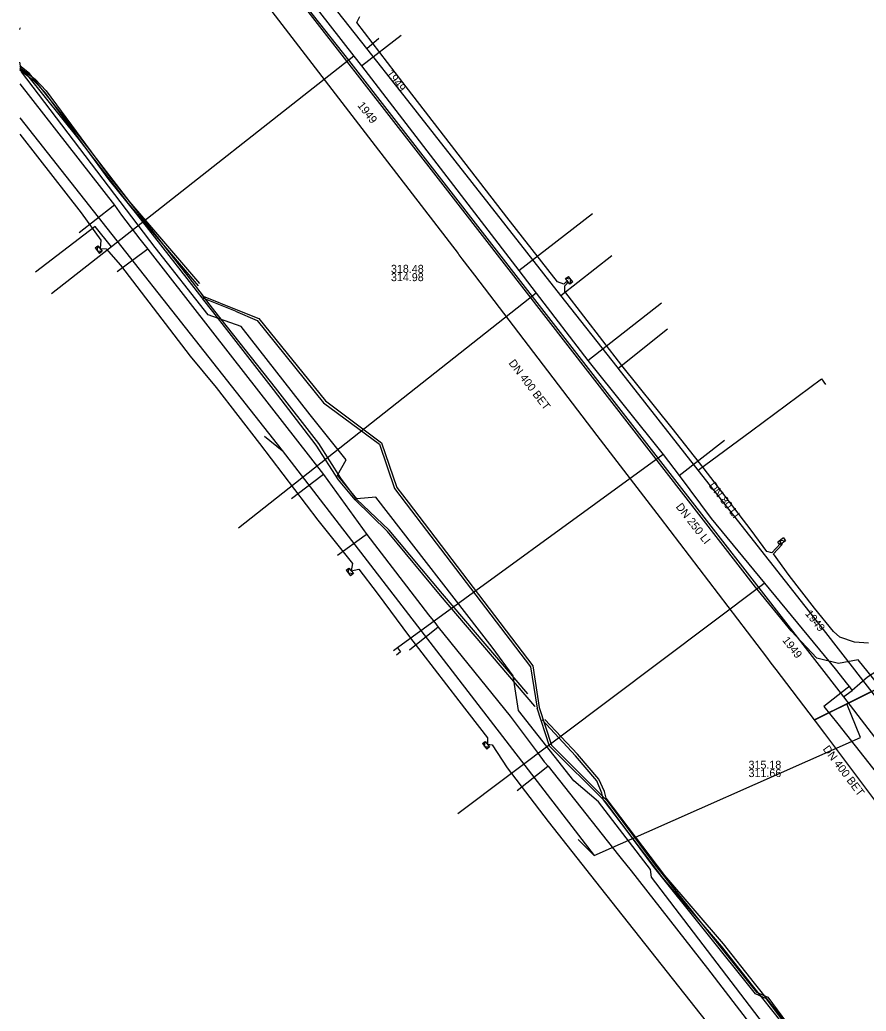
# Model space of a CAD drawing. Extents: x -600391 to -599491, y -1160176 to -1159402.
# Drawn here: x -600391 to -600306.4, y -1160007 to -1159907.9 of the extents above; entities that cross this region are included whole.
import ezdxf

# ---------------------------------------------------------------- set-up
doc = ezdxf.new("R2010")
doc.units = 0
for name, color, linetype in [('31', 7, 'Continuous'), ('Vrstva 1', 7, 'Continuous'), ('Vrstva 12', 7, 'Continuous'), ('Vrstva 13', 7, 'Continuous'), ('Vrstva 15', 7, 'Continuous'), ('Vrstva 16', 7, 'Continuous'), ('Vrstva 19', 7, 'Continuous'), ('Vrstva 42', 7, 'Continuous'), ('Vrstva 43', 7, 'Continuous'), ('Vrstva 44', 7, 'Continuous'), ('Vrstva 55', 7, 'Continuous'), ('Vrstva 9', 7, 'Continuous')]:
    doc.layers.add(name, color=color, linetype=linetype)

# ---------------------------------------------------------------- blocks, each defined once
blk = doc.blocks.new('NN630')
at = {"layer": '31'}
for points in [[(0, -0.7), (-0.7, 0)], [(-0.7, -0.7), (-0.7, 0), (0.7, 0), (0.7, -0.7)], [(-0.7, -0.7), (0.7, -0.7)], [(0, -0.7), (0.7, 0)]]:
    blk.add_lwpolyline(points, dxfattribs=at)

msp = doc.modelspace()

# ---------------------------------------------------------------- linework, layer by layer
at = {"layer": 'Vrstva 1'}
for points in [[(-600391.008, -1159917.713), (-600364.77, -1159950.97), (-600333.59, -1159991.48), (-600306.97, -1159979.68), (-600308.31, -1159976.3)], [(-600366.53, -1159949.54), (-600364.77, -1159950.97)], [(-600311.59, -1159977.93), (-600296.63, -1159970.49)], [(-600335.19, -1159989.88), (-600333.59, -1159991.48)]]:
    msp.add_lwpolyline(points, dxfattribs=at)
at = {"layer": 'Vrstva 13'}
for p, q in [((-600356.844, -1159912.521), (-600352.885, -1159909.449)), ((-600341.125, -1159932.989), (-600333.754, -1159927.265)), ((-600339.371, -1159935.249), (-600369.159, -1159958.739)), ((-600334.21, -1159941.97), (-600326.843, -1159936.208)), ((-600325.089, -1159953.462), (-600320.541, -1159949.955)), ((-600309.48, -1159972.8), (-600308.26, -1159974.37)), ((-600308.39, -1159975.39), (-600307.801, -1159974.957)), ((-600308.26, -1159974.37), (-600308.05, -1159974.6)), ((-600308.05, -1159974.6), (-600307.91, -1159974.82)), ((-600307.91, -1159974.82), (-600307.801, -1159974.957)), ((-600308.661, -1159975.601), (-600308.39, -1159975.39)), ((-600308.661, -1159975.601), (-600303.85, -1159981.9))]:
    msp.add_line(p, q, dxfattribs=at)
for points in [[(-600371.27, -1159895.33), (-600358.149, -1159911.953), (-600339.787, -1159935.576), (-600327.193, -1159951.77), (-600317.13, -1159964.711), (-600308.661, -1159975.601)], [(-600370.56, -1159894.82), (-600366.86, -1159899.69), (-600357.618, -1159911.541), (-600356.844, -1159912.521), (-600341.125, -1159932.989), (-600339.371, -1159935.249), (-600334.21, -1159941.97), (-600326.669, -1159951.391), (-600325.089, -1159953.462), (-600321.88, -1159957.77), (-600316.541, -1159964.251), (-600309.48, -1159972.8)], [(-600357.618, -1159911.541), (-600381.833, -1159930.601), (-600387.827, -1159935.322)], [(-600381.833, -1159930.601), (-600383.466, -1159928.572), (-600389.434, -1159933.139)], [(-600326.669, -1159951.391), (-600353.235, -1159970.718), (-600353.648, -1159971.018)], [(-600271.84, -1159953.73), (-600272.416, -1159954.049), (-600276.96, -1159956.56), (-600296.475, -1159967.676), (-600302.974, -1159971.546), (-600306.244, -1159973.633), (-600307.801, -1159974.957)], [(-600316.541, -1159964.251), (-600316.739, -1159964.415), (-600347.228, -1159987.292)], [(-600353.235, -1159970.718), (-600352.938, -1159971.114), (-600353.346, -1159971.428)], [(-600308.304, -1159974.747), (-600310.606, -1159976.582), (-600309.22, -1159978.29), (-600300.55, -1159989.29), (-600296.77, -1159994.11), (-600294.38, -1159997.18), (-600292.26, -1159999.96), (-600280.7, -1160014.54), (-600273.1, -1160024.31), (-600254.85, -1160047.91), (-600240.71, -1160065.868), (-600236.26, -1160071.52), (-600225.09, -1160085.97)], [(-600308.05, -1159974.6), (-600308.17, -1159974.64), (-600308.304, -1159974.747)]]:
    msp.add_lwpolyline(points, dxfattribs=at)
at = {"layer": 'Vrstva 16'}
for points in [[(-600149.134, -1160176.079), (-600149.77, -1160175.26), (-600153.28, -1160170.92), (-600160.82, -1160161.59), (-600162.37, -1160159.57), (-600191.81, -1160121.42), (-600215.03, -1160091.66), (-600218.37, -1160087.39), (-600241.27, -1160058.04), (-600268.45, -1160023.15), (-600268.66, -1160022.86), (-600279.96, -1160008.45), (-600285.15, -1160001.76), (-600292.76, -1159991.95), (-600306.26, -1159974.55), (-600310.89, -1159968.58), (-600323.17, -1159952.95), (-600331.19, -1159942.75), (-600331.3, -1159942.61), (-600336.91, -1159935.47), (-600352.95, -1159915.04), (-600356.32, -1159910.78), (-600372.09, -1159890.83), (-600376.451, -1159885.301)], [(-600356.32, -1159910.78), (-600355.108, -1159909.736)], [(-600336.91, -1159935.47), (-600331.83, -1159931.48)], [(-600331.19, -1159942.75), (-600331.05, -1159942.64), (-600326.25, -1159938.8)], [(-600323.17, -1159952.95), (-600317.85, -1159949), (-600310.85, -1159943.8), (-600310.44, -1159944.37)]]:
    msp.add_lwpolyline(points, dxfattribs=at)
at = {"layer": 'Vrstva 19'}
for points in [[(-600391.008, -1159914.325), (-600381.529, -1159926.451), (-600380.833, -1159927.445), (-600379.008, -1159929.852), (-600378.217, -1159930.849), (-600369.989, -1159941.398), (-600360.656, -1159953.378), (-600356.31, -1159959.38), (-600350.146, -1159967.417), (-600349.517, -1159968.18), (-600349.17, -1159968.626), (-600341.976, -1159977.525), (-600339.196, -1159981.285), (-600338.575, -1159982.09), (-600338.198, -1159982.551), (-600331.141, -1159991.444), (-600330.889, -1159991.755), (-600329.884, -1159993.003), (-600322.24, -1160002.783), (-600309.472, -1160019.436)], [(-600381.529, -1159926.451), (-600381.674, -1159926.557), (-600385.076, -1159929.231)], [(-600378.217, -1159930.849), (-600378.441, -1159931.022), (-600381.265, -1159933.11)], [(-600360.656, -1159953.378), (-600360.781, -1159953.469), (-600363.842, -1159955.802)], [(-600356.31, -1159959.38), (-600356.478, -1159959.465), (-600359.244, -1159961.477)], [(-600349.17, -1159968.626), (-600349.352, -1159968.775), (-600352.049, -1159970.939)], [(-600338.198, -1159982.551), (-600338.395, -1159982.708), (-600341.271, -1159984.991)]]:
    msp.add_lwpolyline(points, dxfattribs=at)
at = {"layer": 'Vrstva 42'}
for points in [[(-600306.14, -1159970.25), (-600307.56, -1159970.14), (-600309.02, -1159969.64), (-600309.64, -1159969.07), (-600311.55, -1159966.75), (-600314.1, -1159963.48), (-600315.661, -1159961.312), (-600314.806, -1159960.423), (-600314.739, -1159960.21), (-600314.95, -1159960.285), (-600315.831, -1159961.201), (-600316.33, -1159961.07), (-600317.9, -1159958.95), (-600322.7, -1159952.66), (-600325.8, -1159948.74), (-600330.82, -1159942.49), (-600336.52, -1159935.09), (-600336.512, -1159934.519), (-600336.284, -1159934.274), (-600336.22, -1159934.06), (-600336.43, -1159934.138), (-600336.612, -1159934.333), (-600337.25, -1159934.1), (-600342.31, -1159927.64), (-600352.73, -1159914.2), (-600357.33, -1159908.2), (-600357.02, -1159907.6)], [(-600391.008, -1159919.342), (-600389.25, -1159921.63), (-600384.89, -1159927.21), (-600382.9, -1159929.96), (-600382.98, -1159930.78), (-600382.36, -1159930.81), (-600380.95, -1159932.44), (-600373.97, -1159941.55), (-600371.37, -1159944.67), (-600367.03, -1159950.29), (-600361.22, -1159957.95), (-600357.75, -1159962.28), (-600357.88, -1159963), (-600357.12, -1159962.83), (-600355.28, -1159965.23), (-600352.06, -1159969.61), (-600347.116, -1159976.002), (-600344.24, -1159979.72), (-600344.26, -1159980.34), (-600343.77, -1159980.4), (-600342.29, -1159982.7), (-600338.18, -1159988.08), (-600332.96, -1159994.69), (-600318.5, -1160013)]]:
    msp.add_lwpolyline(points, dxfattribs=at)
at = {"layer": 'Vrstva 44'}
for points in [[(-600373.025, -1159934.291), (-600380, -1159926.12), (-600385.01, -1159919.61), (-600390.03, -1159913.3), (-600391.008, -1159912.504)], [(-600391.008, -1159912.7), (-600389.48, -1159913.854), (-600388.37, -1159915.015), (-600381.908, -1159923.788), (-600379.169, -1159927.217), (-600374.108, -1159933.668), (-600372.664, -1159935.537), (-600369.379, -1159936.876)], [(-600373.152, -1159934.506), (-600380.18, -1159926.26), (-600385.17, -1159919.75), (-600390.2, -1159913.5), (-600391.008, -1159912.826)], [(-600369.455, -1159937.062), (-600372.79, -1159935.701), (-600374.266, -1159933.79), (-600379.325, -1159927.341), (-600382.066, -1159923.91), (-600388.524, -1159915.143), (-600389.614, -1159914.004), (-600391.008, -1159912.951)], [(-600340.217, -1159975.311), (-600348.75, -1159965.31), (-600354.07, -1159958.94), (-600357.35, -1159955.84), (-600358.92, -1159953.75), (-600361.12, -1159950.29), (-600365.46, -1159944.7), (-600371.51, -1159937.04), (-600372.766, -1159935.424)], [(-600339.474, -1159976.584), (-600339.51, -1159976.54), (-600348.95, -1159965.46), (-600354.25, -1159959.09), (-600357.48, -1159955.92), (-600359.13, -1159953.91), (-600361.39, -1159950.43), (-600365.66, -1159944.87), (-600371.72, -1159937.09), (-600372.751, -1159935.77)], [(-600369.455, -1159937.062), (-600367.292, -1159937.976), (-600360.632, -1159946.199), (-600355.055, -1159950.353), (-600353.532, -1159954.788), (-600352.366, -1159956.301), (-600339.944, -1159972.598), (-600339.272, -1159976.73)], [(-600369.379, -1159936.876), (-600367.126, -1159937.784), (-600360.457, -1159946.017), (-600354.844, -1159950.199), (-600353.309, -1159954.668), (-600352.168, -1159956.149), (-600339.712, -1159972.49), (-600339.082, -1159976.668)], [(-600314.529, -1160008.243), (-600316.341, -1160005.79), (-600317.469, -1160005.311), (-600327.646, -1159992.57), (-600332.423, -1159986.125), (-600338.035, -1159980.533), (-600339.272, -1159976.73)], [(-600339.082, -1159976.668), (-600337.859, -1159980.425), (-600332.271, -1159985.993), (-600327.488, -1159992.448), (-600317.345, -1160005.147), (-600316.213, -1160005.628), (-600314.345, -1160008.155)], [(-600308.86, -1160015.68), (-600317.75, -1160004.46), (-600320.85, -1160000.52), (-600326.73, -1159993.69), (-600332.64, -1159985.92), (-600332.83, -1159985.24), (-600333.33, -1159984.02), (-600335.46, -1159981.5), (-600338.77, -1159977.915)], [(-600308.56, -1160015.54), (-600317.55, -1160004.22), (-600320.66, -1160000.31), (-600326.53, -1159993.47), (-600332.39, -1159985.73), (-600332.54, -1159985.07), (-600333.13, -1159983.84), (-600335.26, -1159981.35), (-600338.526, -1159977.861)]]:
    msp.add_lwpolyline(points, dxfattribs=at)
at = {"layer": 'Vrstva 55'}
for points in [[(-600281.812, -1160010.273), (-600299.508, -1159987.183), (-600300.16, -1159986.58), (-600301.82, -1159983.47), (-600301.45, -1159978.98), (-600307.18, -1159971.91), (-600309.16, -1159972.27), (-600311.325, -1159971.736), (-600313.891, -1159969.017), (-600317.454, -1159964.632), (-600331.794, -1159946.163), (-600349.159, -1159923.812), (-600366.164, -1159901.927)], [(-600391.008, -1159908.895), (-600390.98, -1159908.75), (-600391.008, -1159908.715)], [(-600311.93, -1160014.51), (-600327.86, -1159993.65), (-600327.94, -1159992.86), (-600333.15, -1159986.11), (-600335.63, -1159983.99), (-600341.16, -1159976.97), (-600341.67, -1159973.49), (-600343.78, -1159970.63), (-600355.42, -1159955.64), (-600357.31, -1159955.8), (-600359.26, -1159953.43), (-600358.38, -1159951.9), (-600361.97, -1159947.4), (-600368.87, -1159938.59), (-600372.18, -1159937.4), (-600377.48, -1159930.69), (-600390.83, -1159913.12), (-600391.008, -1159912.167)]]:
    msp.add_lwpolyline(points, dxfattribs=at)
at = {"layer": 'Vrstva 9'}
msp.add_line((-600311.58, -1159977.9), (-600296.63, -1159970.45), dxfattribs=at)
for points in [[(-600377.81, -1159891.47), (-600355.473, -1159920.528), (-600347.196, -1159931.295), (-600347.117, -1159931.398), (-600346.8, -1159931.81)], [(-600346.8, -1159931.81), (-600346.011, -1159932.843), (-600345.543, -1159933.455), (-600333.309, -1159949.465), (-600327, -1159957.721), (-600316.368, -1159971.634), (-600315.907, -1159972.238), (-600315.427, -1159972.865), (-600311.58, -1159977.9)], [(-600311.58, -1159977.9), (-600310.56, -1159979.26), (-600292.175, -1160003.784), (-600286.458, -1160011.409)]]:
    msp.add_lwpolyline(points, dxfattribs=at)

# ---------------------------------------------------------------- block references
at = {"layer": 'Vrstva 43', "yscale": 0.5}
for p, xscale, rotation in [((-600382.98, -1159930.78), 0.5000000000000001, -50.999999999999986), ((-600336.22, -1159934.06), 0.5, 128), ((-600314.739, -1159960.21), 0.5000000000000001, -143), ((-600357.88, -1159963), 0.5000000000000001, -50.999999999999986), ((-600344.26, -1159980.34), 0.5, -52.000000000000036)]:
    msp.add_blockref('NN630', p, dxfattribs=dict(at, xscale=xscale, rotation=rotation))

# ---------------------------------------------------------------- texts
at = {"layer": 'Vrstva 12'}
for s, p in [('318.48', (-600353.901, -1159933.214)), ('314.98', (-600353.901, -1159934.046)), ('315.18', (-600318.15, -1159982.795)), ('311.66', (-600318.15, -1159983.627))]:
    msp.add_text(s, height=0.8, dxfattribs=at).set_placement(p)
for rotation, p in [(307.39186, (-600342.178, -1159942.248)), (307.10538, (-600310.763, -1159980.834))]:
    msp.add_text('DN 400 BET', height=0.8, rotation=rotation, dxfattribs=at).set_placement(p)
at = {"layer": 'Vrstva 15'}
for s, rotation, p in [('1949', 307.50645, (-600354.415, -1159913.292)), ('1949', 307.85022, (-600357.298, -1159916.493)), ('DN 80 LI', 307.73563, (-600322.172, -1159954.499)), ('DN 250 LI', 307.85022, (-600325.461, -1159956.613)), ('1949', 308.53777, (-600312.537, -1159967.307)), ('1949', 307.85022, (-600314.812, -1159969.962))]:
    msp.add_text(s, height=0.8, rotation=rotation, dxfattribs=at).set_placement(p)

doc.saveas('drawing.dxf')
